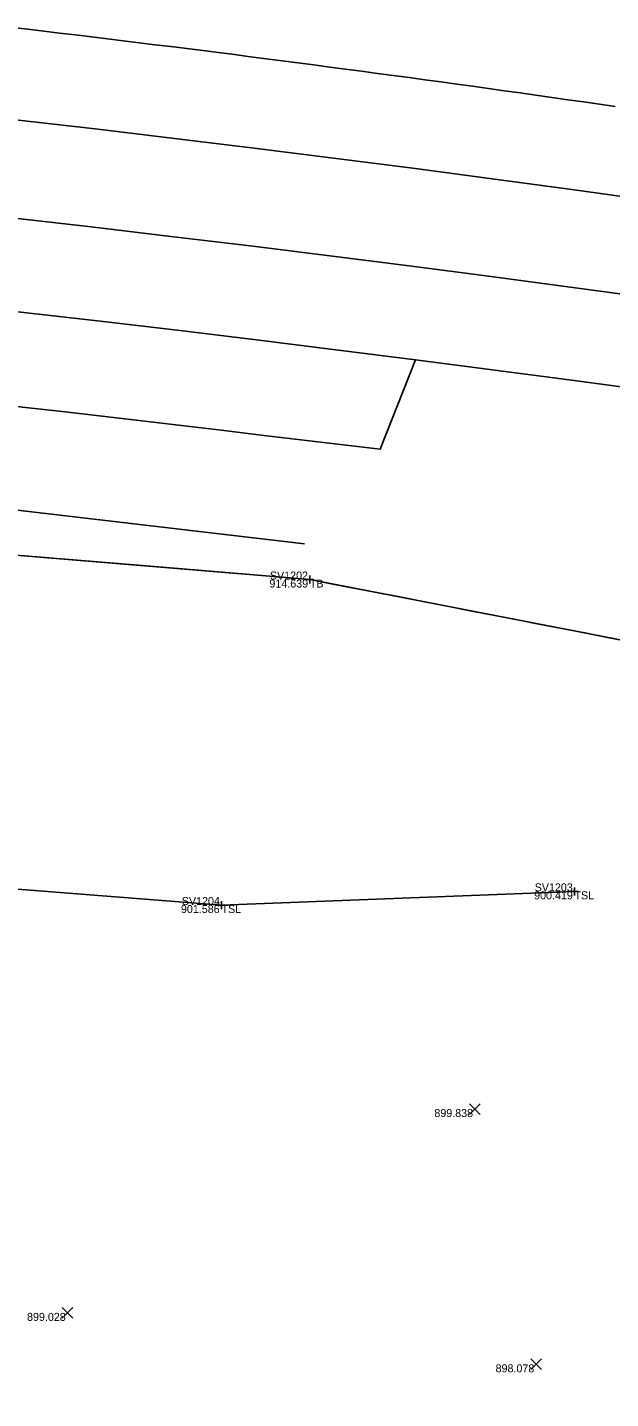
# Model space of a CAD drawing. Extents: x 1918148 to 1919797, y 624701 to 627089.
# Drawn here: x 1919076 to 1919148.9, y 625706.2 to 625877.5 of the extents above; entities that cross this region are included whole.
import ezdxf

# ---------------------------------------------------------------- set-up
doc = ezdxf.new("R2010")
doc.units = 0
for name, color, linetype in [('DT_X_Break_Line', 7, 'Continuous'), ('DT_X_Terrain_Boundary', 7, 'Continuous'), ('PM_X_Channelizing_Line', 7, 'Continuous'), ('PM_X_CL_Double_Solid', 7, 'Continuous'), ('PM_X_Edge_Line', 7, 'Continuous'), ('PM_X_Lane_Line', 7, 'Continuous'), ('RD_X_GR_Rt', 7, 'Continuous'), ('SV_X_Random_Point', 7, 'Continuous'), ('SV_X_Shot_Marker', 7, 'Continuous'), ('SV_X_Text_Comment', 7, 'Continuous'), ('SV_X_Text_Elevation', 7, 'Continuous'), ('SV_X_Text_Name', 7, 'Continuous'), ('SV_X_Toe_of_Slope', 7, 'Continuous'), ('SV_X_Top_of_Bank', 7, 'Continuous')]:
    doc.layers.add(name, color=color, linetype=linetype)

msp = doc.modelspace()

# ---------------------------------------------------------------- linework, layer by layer
at = {"layer": 'DT_X_Break_Line'}
msp.add_lwpolyline([(1919111.29, 625808.54), (1919114.15, 625807.98), (1919117.01, 625807.43), (1919119.87, 625806.87), (1919122.73, 625806.32), (1919125.6, 625805.76), (1919128.46, 625805.2), (1919131.32, 625804.65), (1919134.18, 625804.09), (1919137.04, 625803.53), (1919139.91, 625802.98), (1919142.77, 625802.42), (1919145.63, 625801.86), (1919148.49, 625801.31), (1919151.35, 625800.75)], dxfattribs=at)
at = {"layer": 'DT_X_Terrain_Boundary'}
for points in [[(1919149.44, 625867.64), (1919147.46, 625867.92), (1919145.48, 625868.21), (1919143.5, 625868.49), (1919141.52, 625868.78), (1919139.54, 625869.06), (1919137.56, 625869.34), (1919135.58, 625869.62), (1919133.6, 625869.89), (1919131.62, 625870.17), (1919129.64, 625870.44), (1919127.66, 625870.71), (1919125.68, 625870.99), (1919123.7, 625871.25), (1919121.71, 625871.52), (1919119.73, 625871.79), (1919117.75, 625872.06), (1919115.77, 625872.32), (1919113.78, 625872.58), (1919111.8, 625872.84), (1919109.82, 625873.1), (1919107.83, 625873.36), (1919105.85, 625873.62), (1919103.87, 625873.87), (1919101.88, 625874.13), (1919099.9, 625874.38), (1919097.92, 625874.63), (1919095.93, 625874.88), (1919093.95, 625875.13), (1919091.96, 625875.37), (1919089.98, 625875.62), (1919087.99, 625875.86), (1919086.01, 625876.1), (1919084.02, 625876.34), (1919082.04, 625876.58), (1919080.05, 625876.82), (1919078.06, 625877.06), (1919076.08, 625877.29), (1919074.09, 625877.53)], [(1919200.65, 625791.17), (1919111.29, 625808.54), (1919090.36, 625810.28), (1919065.45, 625812.35), (1919063.39, 625820.89), (1919065.48, 625831.23), (1919070.44, 625830.66), (1919075.41, 625830.09), (1919080.38, 625829.52), (1919085.35, 625828.96), (1919090.31, 625828.39), (1919095.28, 625827.8), (1919100.24, 625827.2), (1919105.21, 625826.6), (1919110.17, 625826), (1919115.14, 625825.41), (1919120.1, 625824.81), (1919124.48, 625836), (1919134.4, 625834.72), (1919144.31, 625833.4), (1919154.22, 625832.06)]]:
    msp.add_lwpolyline(points, dxfattribs=at)
at = {"layer": 'PM_X_Channelizing_Line'}
msp.add_lwpolyline([(1918955.09, 625877.37), (1918965.06, 625876.6), (1918975.03, 625875.79), (1918984.99, 625874.95), (1918994.95, 625874.08), (1919004.91, 625873.18), (1919014.87, 625872.24), (1919024.82, 625871.28), (1919034.77, 625870.28), (1919044.72, 625869.26), (1919054.67, 625868.2), (1919064.61, 625867.11), (1919074.54, 625865.99), (1919084.48, 625864.84), (1919094.41, 625863.66), (1919104.33, 625862.45), (1919114.25, 625861.2), (1919124.17, 625859.93), (1919134.09, 625858.62), (1919144, 625857.29), (1919153.9, 625855.92), (1919160.39, 625855.01)], dxfattribs=at)
at = {"layer": 'PM_X_CL_Double_Solid'}
msp.add_lwpolyline([(1918954.64, 625865.34), (1918964.6, 625864.53), (1918974.57, 625863.69), (1918984.53, 625862.82), (1918994.49, 625861.93), (1919004.45, 625861), (1919014.4, 625860.05), (1919024.35, 625859.07), (1919034.3, 625858.06), (1919044.25, 625857.03), (1919054.19, 625855.96), (1919064.13, 625854.87), (1919074.07, 625853.75), (1919084, 625852.6), (1919093.93, 625851.42), (1919103.86, 625850.22), (1919113.79, 625848.98), (1919123.71, 625847.72), (1919133.62, 625846.43), (1919143.53, 625845.11), (1919153.44, 625843.77), (1919160.7, 625842.77)], dxfattribs=at)
at = {"layer": 'PM_X_Edge_Line'}
for points in [[(1919074.09, 625877.53), (1919076.08, 625877.29), (1919078.06, 625877.06), (1919080.05, 625876.82), (1919082.04, 625876.58), (1919084.02, 625876.34), (1919086.01, 625876.1), (1919087.99, 625875.86), (1919089.98, 625875.62), (1919091.96, 625875.37), (1919093.95, 625875.13), (1919095.93, 625874.88), (1919097.92, 625874.63), (1919099.9, 625874.38), (1919101.88, 625874.13), (1919103.87, 625873.87), (1919105.85, 625873.62), (1919107.83, 625873.36), (1919109.82, 625873.1), (1919111.8, 625872.84), (1919113.78, 625872.58), (1919115.77, 625872.32), (1919117.75, 625872.06), (1919119.73, 625871.79), (1919121.71, 625871.52), (1919123.7, 625871.25), (1919125.68, 625870.99), (1919127.66, 625870.71), (1919129.64, 625870.44), (1919131.62, 625870.17), (1919133.6, 625869.89), (1919135.58, 625869.62), (1919137.56, 625869.34), (1919139.54, 625869.06), (1919141.52, 625868.78), (1919143.5, 625868.49), (1919145.48, 625868.21), (1919147.46, 625867.92), (1919149.44, 625867.64)], [(1919120.1, 625824.81), (1919115.14, 625825.41), (1919110.17, 625826), (1919105.21, 625826.6), (1919100.24, 625827.2), (1919095.28, 625827.8), (1919090.31, 625828.39), (1919085.35, 625828.96), (1919080.38, 625829.52), (1919075.41, 625830.09)]]:
    msp.add_lwpolyline(points, dxfattribs=at)
at = {"layer": 'PM_X_Lane_Line'}
msp.add_lwpolyline([(1918955.39, 625853.42), (1918965.36, 625852.63), (1918975.33, 625851.81), (1918985.29, 625850.96), (1918995.25, 625850.08), (1919005.21, 625849.17), (1919015.17, 625848.23), (1919025.12, 625847.27), (1919035.07, 625846.27), (1919045.02, 625845.25), (1919054.96, 625844.19), (1919064.9, 625843.11), (1919074.84, 625842), (1919084.78, 625840.86), (1919094.71, 625839.69), (1919104.63, 625838.49), (1919114.56, 625837.26), (1919124.48, 625836), (1919134.4, 625834.72), (1919144.31, 625833.4), (1919154.22, 625832.06), (1919164.12, 625830.68), (1919174.03, 625829.28), (1919193.35, 625826.46)], dxfattribs=at)
at = {"layer": 'RD_X_GR_Rt'}
msp.add_lwpolyline([(1918971.66, 625826.7), (1918985.81, 625826.14), (1919053.44, 625819.71), (1919110.63, 625813)], dxfattribs=at)
at = {"layer": 'SV_X_Random_Point'}
for p, q in [((1919131.24, 625741.71), (1919132.57, 625743.04)), ((1919131.24, 625743.04), (1919132.57, 625741.71)), ((1919080.37, 625716.24), (1919081.7, 625717.57)), ((1919080.37, 625717.57), (1919081.7, 625716.24)), ((1919138.89, 625709.82), (1919140.22, 625711.15)), ((1919138.89, 625711.15), (1919140.22, 625709.82))]:
    msp.add_line(p, q, dxfattribs=at)
at = {"layer": 'SV_X_Shot_Marker'}
for p, q in [((1919110.79, 625808.54), (1919111.79, 625808.54)), ((1919111.29, 625809.04), (1919111.29, 625808.04)), ((1919111.29, 625808.54), (1919111.29, 625808.54)), ((1919143.85, 625769.58), (1919144.85, 625769.58)), ((1919144.35, 625770.08), (1919144.35, 625769.08)), ((1919144.35, 625769.58), (1919144.35, 625769.58)), ((1919099.77, 625767.87), (1919100.77, 625767.87)), ((1919100.27, 625768.37), (1919100.27, 625767.37)), ((1919100.27, 625767.87), (1919100.27, 625767.87))]:
    msp.add_line(p, q, dxfattribs=at)
at = {"layer": 'SV_X_Toe_of_Slope'}
msp.add_lwpolyline([(1919144.35, 625769.58), (1919100.27, 625767.87), (1919060.95, 625770.93), (1919021.62, 625778.27), (1918998.32, 625779.77), (1918985.02, 625778.23), (1918981.12, 625762.93), (1918979.64, 625746.6), (1918992.24, 625715.18), (1919001.08, 625693.54), (1919008.19, 625681.54), (1919013.95, 625671.92), (1919018.79, 625665.98), (1919022.16, 625659.12), (1919025.26, 625652.5), (1919028.92, 625643.15)], dxfattribs=at)
at = {"layer": 'SV_X_Top_of_Bank'}
msp.add_lwpolyline([(1919180.03, 625377.77), (1919142.39, 625420.85), (1919113.9, 625458.17), (1919086.6, 625489.42), (1919057.39, 625523.08), (1919019.76, 625570.22), (1918998.07, 625602.27), (1918985.26, 625627.56), (1918968.39, 625668.03), (1918955.62, 625707.63), (1918947.9, 625739.17), (1918945.04, 625765.59), (1918947.37, 625785.94), (1918957.93, 625802.75), (1918975.61, 625809.21), (1918997.58, 625813.39), (1919030.67, 625814.44), (1919065.45, 625812.35), (1919111.29, 625808.54)], dxfattribs=at)

# ---------------------------------------------------------------- texts
at = {"layer": 'SV_X_Text_Comment'}
for s, p in [('TB', (1919111.29, 625807.54)), ('TSL', (1919144.35, 625768.58)), ('TSL', (1919100.27, 625766.87))]:
    msp.add_text(s, height=1, dxfattribs=at).set_placement(p)
at = {"layer": 'SV_X_Text_Elevation'}
for s, p in [('914.639', (1919106.25, 625807.54)), ('900.419', (1919139.31, 625768.58)), ('901.586', (1919095.2, 625766.87)), ('899.838', (1919126.85, 625741.38)), ('899.028', (1919075.98, 625715.91)), ('898.078', (1919134.5, 625709.48))]:
    msp.add_text(s, height=1, dxfattribs=at).set_placement(p)
at = {"layer": 'SV_X_Text_Name'}
for s, p in [('SV1202', (1919106.31, 625808.54)), ('SV1203', (1919139.38, 625769.58)), ('SV1204', (1919095.31, 625767.87))]:
    msp.add_text(s, height=1, dxfattribs=at).set_placement(p)

doc.saveas('drawing.dxf')
